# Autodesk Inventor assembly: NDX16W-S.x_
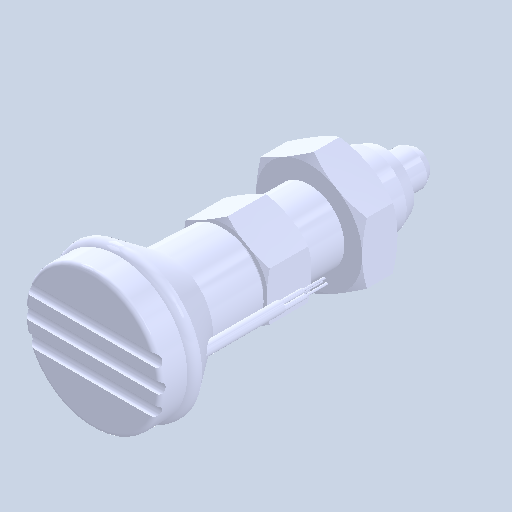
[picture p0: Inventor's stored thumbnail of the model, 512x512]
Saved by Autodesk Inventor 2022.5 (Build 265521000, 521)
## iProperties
Created: 2024-05
Part Number: NDX16W-S.x_
Document SubType Name: Assembly
Designer: ImaoCorp
Author: ImaoCorp
Sending System: SOLIDWORKS 2022-2022290
MC: AMD64
MC_MODEL: Intel64 Family 6 Model 60 Stepping 3, GenuineIntel
OS: Windows_NT
FRU: Parasolid Version 33.1, build 260,  4-25-2022
FORMAT: text
GUISE: transmit
KEY: FILENDX16W-S.x_t
DATE: Tue May 21 08:47:41 2024
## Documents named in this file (3)
- X:\14_SW2022-Inv2022\保留中\kipp\KME_データ\n\ndx16w-s\NDX16W-S.x_.iam
- X:\14_SW2022-Inv2022\保留中\kipp\KME_データ\n\ndx16w-s\NDX16W-S_01.ipt
- X:\14_SW2022-Inv2022\保留中\kipp\KME_データ\n\ndx16w-s\NDX16W-S_02.ipt
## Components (2 placed, 2 different names)
1. NDX16W-S_01
2. NDX16W-S_02
